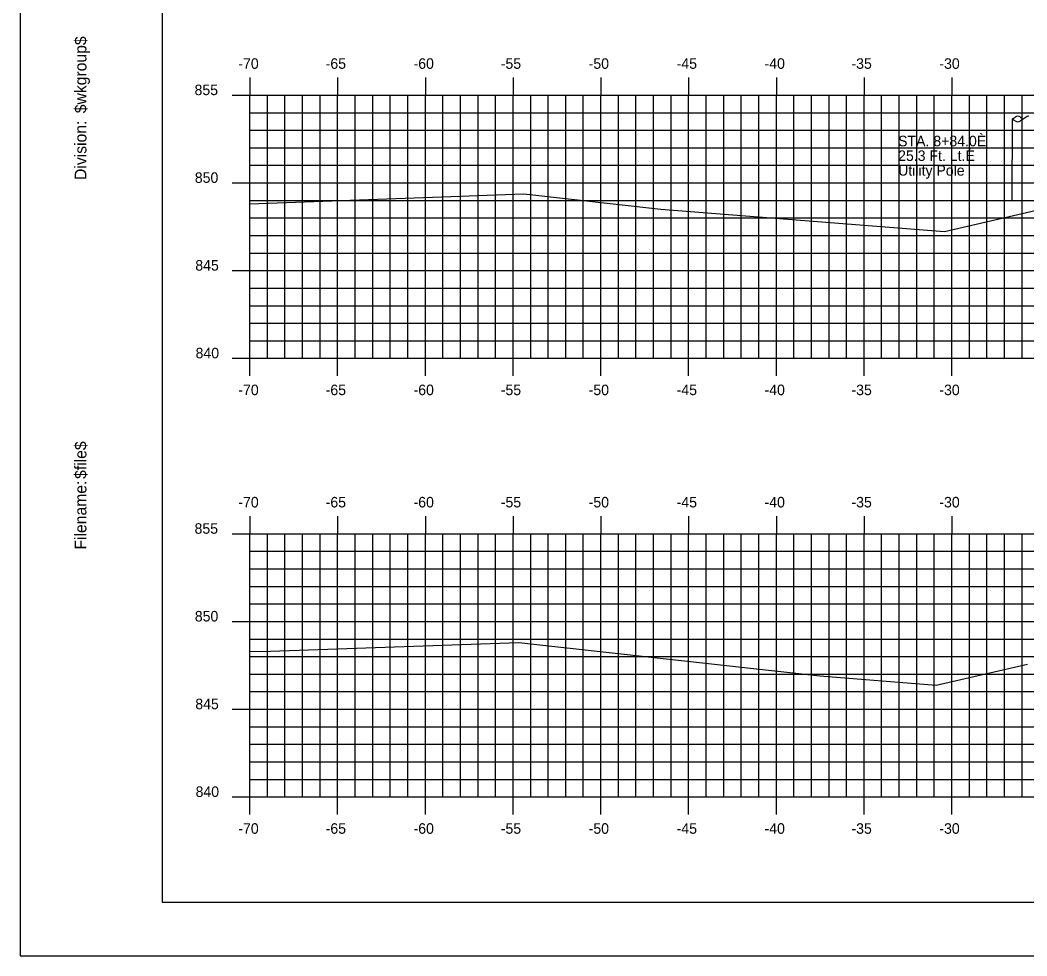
# Model space of a CAD drawing. Extents: x 2194502 to 2194968, y 863888 to 863998.
# Drawn here: x 2194615.4 to 2194672.8, y 863888.4 to 863941.7 of the extents above; entities that cross this region are included whole.
import ezdxf

# ---------------------------------------------------------------- set-up
doc = ezdxf.new("R2010")
doc.units = 0
for name, color, linetype in [('BORDER', 7, 'Continuous'), ('D_Text_Monospaced', 7, 'Continuous'), ('H_V ANNOTATION', 7, 'Continuous'), ('MAJOR', 7, 'Continuous'), ('MINOR', 7, 'Continuous'), ('PLOT BOUNDARY', 7, 'Continuous'), ('S_Roadway_Centerline', 7, 'Continuous'), ('S_Utilities_Pole_Power', 7, 'Continuous')]:
    doc.layers.add(name, color=color, linetype=linetype)

msp = doc.modelspace()

# ---------------------------------------------------------------- linework, layer by layer
at = {"layer": 'BORDER'}
msp.add_lwpolyline([(2194623.499, 863891.446), (2194783.499, 863891.446), (2194783.499, 863996.446), (2194623.499, 863996.446)], close=True, dxfattribs=at)
at = {"layer": 'MAJOR'}
for p, q in [((2194628.499, 863938.448), (2194628.499, 863937.446)), ((2194633.499, 863938.448), (2194633.499, 863937.446)), ((2194638.499, 863938.448), (2194638.499, 863937.446)), ((2194643.499, 863938.448), (2194643.499, 863937.446)), ((2194648.499, 863938.448), (2194648.499, 863937.446)), ((2194653.499, 863938.448), (2194653.499, 863937.446)), ((2194658.499, 863938.448), (2194658.499, 863937.446)), ((2194663.499, 863938.448), (2194663.499, 863937.446)), ((2194668.499, 863938.448), (2194668.499, 863937.446)), ((2194627.497, 863937.446), (2194628.499, 863937.446)), ((2194628.499, 863937.446), (2194768.499, 863937.446)), ((2194628.499, 863922.446), (2194628.499, 863937.446)), ((2194628.499, 863922.446), (2194628.499, 863937.446)), ((2194633.499, 863922.446), (2194633.499, 863937.446)), ((2194638.499, 863922.446), (2194638.499, 863937.446)), ((2194643.499, 863922.446), (2194643.499, 863937.446)), ((2194648.499, 863922.446), (2194648.499, 863937.446)), ((2194653.499, 863922.446), (2194653.499, 863937.446)), ((2194658.499, 863922.446), (2194658.499, 863937.446)), ((2194663.499, 863922.446), (2194663.499, 863937.446)), ((2194668.499, 863922.446), (2194668.499, 863937.446)), ((2194627.497, 863932.446), (2194628.499, 863932.446)), ((2194628.499, 863932.446), (2194768.499, 863932.446)), ((2194627.497, 863927.446), (2194628.499, 863927.446)), ((2194628.499, 863927.446), (2194768.499, 863927.446)), ((2194627.497, 863922.446), (2194628.499, 863922.446)), ((2194628.499, 863922.446), (2194768.499, 863922.446)), ((2194628.499, 863921.444), (2194628.499, 863922.446)), ((2194633.499, 863921.444), (2194633.499, 863922.446)), ((2194638.499, 863921.444), (2194638.499, 863922.446)), ((2194643.499, 863921.444), (2194643.499, 863922.446)), ((2194648.499, 863921.444), (2194648.499, 863922.446)), ((2194653.499, 863921.444), (2194653.499, 863922.446)), ((2194658.499, 863921.444), (2194658.499, 863922.446)), ((2194663.499, 863921.444), (2194663.499, 863922.446)), ((2194668.499, 863921.444), (2194668.499, 863922.446)), ((2194628.499, 863913.448), (2194628.499, 863912.446)), ((2194633.499, 863913.448), (2194633.499, 863912.446)), ((2194638.499, 863913.448), (2194638.499, 863912.446)), ((2194643.499, 863913.448), (2194643.499, 863912.446)), ((2194648.499, 863913.448), (2194648.499, 863912.446)), ((2194653.499, 863913.448), (2194653.499, 863912.446)), ((2194658.499, 863913.448), (2194658.499, 863912.446)), ((2194663.499, 863913.448), (2194663.499, 863912.446)), ((2194668.499, 863913.448), (2194668.499, 863912.446)), ((2194627.497, 863912.446), (2194628.499, 863912.446)), ((2194628.499, 863912.446), (2194768.499, 863912.446)), ((2194628.499, 863897.446), (2194628.499, 863912.446)), ((2194628.499, 863897.446), (2194628.499, 863912.446)), ((2194633.499, 863897.446), (2194633.499, 863912.446)), ((2194638.499, 863897.446), (2194638.499, 863912.446)), ((2194643.499, 863897.446), (2194643.499, 863912.446)), ((2194648.499, 863897.446), (2194648.499, 863912.446)), ((2194653.499, 863897.446), (2194653.499, 863912.446)), ((2194658.499, 863897.446), (2194658.499, 863912.446)), ((2194663.499, 863897.446), (2194663.499, 863912.446)), ((2194668.499, 863897.446), (2194668.499, 863912.446)), ((2194627.497, 863907.446), (2194628.499, 863907.446)), ((2194628.499, 863907.446), (2194768.499, 863907.446)), ((2194627.497, 863902.446), (2194628.499, 863902.446)), ((2194628.499, 863902.446), (2194768.499, 863902.446)), ((2194627.497, 863897.446), (2194628.499, 863897.446)), ((2194628.499, 863897.446), (2194768.499, 863897.446)), ((2194628.499, 863896.444), (2194628.499, 863897.446)), ((2194633.499, 863896.444), (2194633.499, 863897.446)), ((2194638.499, 863896.444), (2194638.499, 863897.446)), ((2194643.499, 863896.444), (2194643.499, 863897.446)), ((2194648.499, 863896.444), (2194648.499, 863897.446)), ((2194653.499, 863896.444), (2194653.499, 863897.446)), ((2194658.499, 863896.444), (2194658.499, 863897.446)), ((2194663.499, 863896.444), (2194663.499, 863897.446)), ((2194668.499, 863896.444), (2194668.499, 863897.446))]:
    msp.add_line(p, q, dxfattribs=at)
at = {"layer": 'MINOR'}
for p, q in [((2194629.499, 863922.446), (2194629.499, 863937.446)), ((2194630.499, 863922.446), (2194630.499, 863937.446)), ((2194631.499, 863922.446), (2194631.499, 863937.446)), ((2194632.499, 863922.446), (2194632.499, 863937.446)), ((2194634.499, 863922.446), (2194634.499, 863937.446)), ((2194635.499, 863922.446), (2194635.499, 863937.446)), ((2194636.499, 863922.446), (2194636.499, 863937.446)), ((2194637.499, 863922.446), (2194637.499, 863937.446)), ((2194639.499, 863922.446), (2194639.499, 863937.446)), ((2194640.499, 863922.446), (2194640.499, 863937.446)), ((2194641.499, 863922.446), (2194641.499, 863937.446)), ((2194642.499, 863922.446), (2194642.499, 863937.446)), ((2194644.499, 863922.446), (2194644.499, 863937.446)), ((2194645.499, 863922.446), (2194645.499, 863937.446)), ((2194646.499, 863922.446), (2194646.499, 863937.446)), ((2194647.499, 863922.446), (2194647.499, 863937.446)), ((2194649.499, 863922.446), (2194649.499, 863937.446)), ((2194650.499, 863922.446), (2194650.499, 863937.446)), ((2194651.499, 863922.446), (2194651.499, 863937.446)), ((2194652.499, 863922.446), (2194652.499, 863937.446)), ((2194654.499, 863922.446), (2194654.499, 863937.446)), ((2194655.499, 863922.446), (2194655.499, 863937.446)), ((2194656.499, 863922.446), (2194656.499, 863937.446)), ((2194657.499, 863922.446), (2194657.499, 863937.446)), ((2194659.499, 863922.446), (2194659.499, 863937.446)), ((2194660.499, 863922.446), (2194660.499, 863937.446)), ((2194661.499, 863922.446), (2194661.499, 863937.446)), ((2194662.499, 863922.446), (2194662.499, 863937.446)), ((2194664.499, 863922.446), (2194664.499, 863937.446)), ((2194665.499, 863922.446), (2194665.499, 863937.446)), ((2194666.499, 863922.446), (2194666.499, 863937.446)), ((2194667.499, 863922.446), (2194667.499, 863937.446)), ((2194669.499, 863922.446), (2194669.499, 863937.446)), ((2194670.499, 863922.446), (2194670.499, 863937.446)), ((2194671.499, 863922.446), (2194671.499, 863937.446)), ((2194672.499, 863922.446), (2194672.499, 863937.446)), ((2194628.499, 863936.446), (2194768.499, 863936.446)), ((2194628.499, 863936.446), (2194629.501, 863936.446)), ((2194628.499, 863935.446), (2194768.499, 863935.446)), ((2194628.499, 863935.446), (2194629.501, 863935.446)), ((2194628.499, 863934.446), (2194768.499, 863934.446)), ((2194628.499, 863934.446), (2194629.501, 863934.446)), ((2194628.499, 863933.446), (2194768.499, 863933.446)), ((2194628.499, 863933.446), (2194629.501, 863933.446)), ((2194628.499, 863931.446), (2194768.499, 863931.446)), ((2194628.499, 863931.446), (2194629.501, 863931.446)), ((2194628.499, 863930.446), (2194768.499, 863930.446)), ((2194628.499, 863930.446), (2194629.501, 863930.446)), ((2194628.499, 863929.446), (2194768.499, 863929.446)), ((2194628.499, 863929.446), (2194629.501, 863929.446)), ((2194628.499, 863928.446), (2194768.499, 863928.446)), ((2194628.499, 863928.446), (2194629.501, 863928.446)), ((2194628.499, 863926.446), (2194768.499, 863926.446)), ((2194628.499, 863926.446), (2194629.501, 863926.446)), ((2194628.499, 863925.446), (2194768.499, 863925.446)), ((2194628.499, 863925.446), (2194629.501, 863925.446)), ((2194628.499, 863924.446), (2194768.499, 863924.446)), ((2194628.499, 863924.446), (2194629.501, 863924.446)), ((2194628.499, 863923.446), (2194768.499, 863923.446)), ((2194628.499, 863923.446), (2194629.501, 863923.446)), ((2194629.499, 863897.446), (2194629.499, 863912.446)), ((2194630.499, 863897.446), (2194630.499, 863912.446)), ((2194631.499, 863897.446), (2194631.499, 863912.446)), ((2194632.499, 863897.446), (2194632.499, 863912.446)), ((2194634.499, 863897.446), (2194634.499, 863912.446)), ((2194635.499, 863897.446), (2194635.499, 863912.446)), ((2194636.499, 863897.446), (2194636.499, 863912.446)), ((2194637.499, 863897.446), (2194637.499, 863912.446)), ((2194639.499, 863897.446), (2194639.499, 863912.446)), ((2194640.499, 863897.446), (2194640.499, 863912.446)), ((2194641.499, 863897.446), (2194641.499, 863912.446)), ((2194642.499, 863897.446), (2194642.499, 863912.446)), ((2194644.499, 863897.446), (2194644.499, 863912.446)), ((2194645.499, 863897.446), (2194645.499, 863912.446)), ((2194646.499, 863897.446), (2194646.499, 863912.446)), ((2194647.499, 863897.446), (2194647.499, 863912.446)), ((2194649.499, 863897.446), (2194649.499, 863912.446)), ((2194650.499, 863897.446), (2194650.499, 863912.446)), ((2194651.499, 863897.446), (2194651.499, 863912.446)), ((2194652.499, 863897.446), (2194652.499, 863912.446)), ((2194654.499, 863897.446), (2194654.499, 863912.446)), ((2194655.499, 863897.446), (2194655.499, 863912.446)), ((2194656.499, 863897.446), (2194656.499, 863912.446)), ((2194657.499, 863897.446), (2194657.499, 863912.446)), ((2194659.499, 863897.446), (2194659.499, 863912.446)), ((2194660.499, 863897.446), (2194660.499, 863912.446)), ((2194661.499, 863897.446), (2194661.499, 863912.446)), ((2194662.499, 863897.446), (2194662.499, 863912.446)), ((2194664.499, 863897.446), (2194664.499, 863912.446)), ((2194665.499, 863897.446), (2194665.499, 863912.446)), ((2194666.499, 863897.446), (2194666.499, 863912.446)), ((2194667.499, 863897.446), (2194667.499, 863912.446)), ((2194669.499, 863897.446), (2194669.499, 863912.446)), ((2194670.499, 863897.446), (2194670.499, 863912.446)), ((2194671.499, 863897.446), (2194671.499, 863912.446)), ((2194672.499, 863897.446), (2194672.499, 863912.446)), ((2194628.499, 863911.446), (2194768.499, 863911.446)), ((2194628.499, 863911.446), (2194629.501, 863911.446)), ((2194628.499, 863910.446), (2194768.499, 863910.446)), ((2194628.499, 863910.446), (2194629.501, 863910.446)), ((2194628.499, 863909.446), (2194768.499, 863909.446)), ((2194628.499, 863909.446), (2194629.501, 863909.446)), ((2194628.499, 863908.446), (2194768.499, 863908.446)), ((2194628.499, 863908.446), (2194629.501, 863908.446)), ((2194628.499, 863906.446), (2194768.499, 863906.446)), ((2194628.499, 863906.446), (2194629.501, 863906.446)), ((2194628.499, 863905.446), (2194768.499, 863905.446)), ((2194628.499, 863905.446), (2194629.501, 863905.446)), ((2194628.499, 863904.446), (2194768.499, 863904.446)), ((2194628.499, 863904.446), (2194629.501, 863904.446)), ((2194628.499, 863903.446), (2194768.499, 863903.446)), ((2194628.499, 863903.446), (2194629.501, 863903.446)), ((2194628.499, 863901.446), (2194768.499, 863901.446)), ((2194628.499, 863901.446), (2194629.501, 863901.446)), ((2194628.499, 863900.446), (2194768.499, 863900.446)), ((2194628.499, 863900.446), (2194629.501, 863900.446)), ((2194628.499, 863899.446), (2194768.499, 863899.446)), ((2194628.499, 863899.446), (2194629.501, 863899.446)), ((2194628.499, 863898.446), (2194768.499, 863898.446)), ((2194628.499, 863898.446), (2194629.501, 863898.446))]:
    msp.add_line(p, q, dxfattribs=at)
at = {"layer": 'PLOT BOUNDARY'}
msp.add_lwpolyline([(2194615.406, 863888.387), (2194785.406, 863888.387), (2194785.406, 863998.387), (2194615.406, 863998.387)], close=True, dxfattribs=at)
at = {"layer": 'S_Roadway_Centerline'}
for points in [[(2194628.499, 863931.248), (2194644.102, 863931.812), (2194651.913, 863930.949), (2194668.077, 863929.672), (2194681.104, 863932.691), (2194681.74, 863932.878), (2194687.144, 863933.179), (2194687.162, 863933.181), (2194691.811, 863933.191), (2194698.499, 863933.212), (2194698.585, 863933.211), (2194710.18, 863932.915), (2194712.278, 863932.755), (2194712.76, 863932.719), (2194712.774, 863932.719), (2194718.053, 863932.454), (2194719.251, 863932.444), (2194722.99, 863932.169), (2194730.529, 863930.489), (2194735.351, 863929.559), (2194737.618, 863928.913), (2194750.8, 863926.104), (2194768.499, 863925.832)], [(2194628.499, 863905.756), (2194629.115, 863905.729), (2194643.827, 863906.249), (2194660.968, 863904.341), (2194667.598, 863903.809), (2194672.818, 863905.013)]]:
    msp.add_lwpolyline(points, dxfattribs=at)
at = {"layer": 'S_Utilities_Pole_Power'}
for p, q in [((2194671.945, 863936.084), (2194672.101, 863936.194)), ((2194672.413, 863936.194), (2194672.57, 863936.084)), ((2194672.726, 863936.194), (2194672.57, 863936.084)), ((2194671.945, 863931.464), (2194671.948, 863936.084)), ((2194672.101, 863935.973), (2194671.945, 863936.084)), ((2194672.57, 863936.084), (2194672.413, 863935.973))]:
    msp.add_line(p, q, dxfattribs=at)
for centre, start, end in [((2194672.257, 863935.973), 90, 125.26439), ((2194672.257, 863935.973), 54.73561, 90), ((2194672.882, 863935.973), 90, 125.26439), ((2194672.257, 863936.194), 234.73561, 270), ((2194672.257, 863936.194), 270, 305.26439)]:
    msp.add_arc(centre, 0.271, start, end, dxfattribs=at)

# ---------------------------------------------------------------- texts
at = {"layer": 'BORDER'}
for s, p in [('$wkgroup$', (2194619.184, 863936.415)), ('Division:', (2194619.184, 863932.612)), ('$file$', (2194619.184, 863915.571)), ('Filename:', (2194619.184, 863911.544))]:
    msp.add_text(s, height=0.6696, rotation=90, dxfattribs=at).set_placement(p)
at = {"layer": 'D_Text_Monospaced'}
for s, p in [('STA. 8+84.0È', (2194665.437, 863934.531)), ('25.3 Ft. Lt.È', (2194665.437, 863933.697)), ('Utility Pole', (2194665.437, 863932.857))]:
    msp.add_text(s, height=0.59998, dxfattribs=at).set_placement(p)
at = {"layer": 'H_V ANNOTATION'}
for s, p in [('-70', (2194627.841, 863938.946)), ('-65', (2194632.817, 863938.946)), ('-60', (2194637.825, 863938.946)), ('-55', (2194642.795, 863938.946)), ('-50', (2194647.803, 863938.946)), ('-45', (2194652.817, 863938.946)), ('-40', (2194657.825, 863938.946)), ('-35', (2194662.779, 863938.946)), ('-30', (2194667.787, 863938.946)), ('855', (2194625.345, 863937.446)), ('850', (2194625.361, 863932.446)), ('845', (2194625.388, 863927.446)), ('840', (2194625.404, 863922.446)), ('-70', (2194627.841, 863920.346)), ('-65', (2194632.817, 863920.346)), ('-60', (2194637.825, 863920.346)), ('-55', (2194642.795, 863920.346)), ('-50', (2194647.803, 863920.346)), ('-45', (2194652.817, 863920.346)), ('-40', (2194657.825, 863920.346)), ('-35', (2194662.779, 863920.346)), ('-30', (2194667.787, 863920.346)), ('-70', (2194627.841, 863913.946)), ('-65', (2194632.817, 863913.946)), ('-60', (2194637.825, 863913.946)), ('-55', (2194642.795, 863913.946)), ('-50', (2194647.803, 863913.946)), ('-45', (2194652.817, 863913.946)), ('-40', (2194657.825, 863913.946)), ('-35', (2194662.779, 863913.946)), ('-30', (2194667.787, 863913.946)), ('855', (2194625.345, 863912.446)), ('850', (2194625.361, 863907.446)), ('845', (2194625.388, 863902.446)), ('840', (2194625.404, 863897.446)), ('-70', (2194627.841, 863895.346)), ('-65', (2194632.817, 863895.346)), ('-60', (2194637.825, 863895.346)), ('-55', (2194642.795, 863895.346)), ('-50', (2194647.803, 863895.346)), ('-45', (2194652.817, 863895.346)), ('-40', (2194657.825, 863895.346)), ('-35', (2194662.779, 863895.346)), ('-30', (2194667.787, 863895.346))]:
    msp.add_text(s, height=0.6, dxfattribs=at).set_placement(p)

doc.saveas('drawing.dxf')
